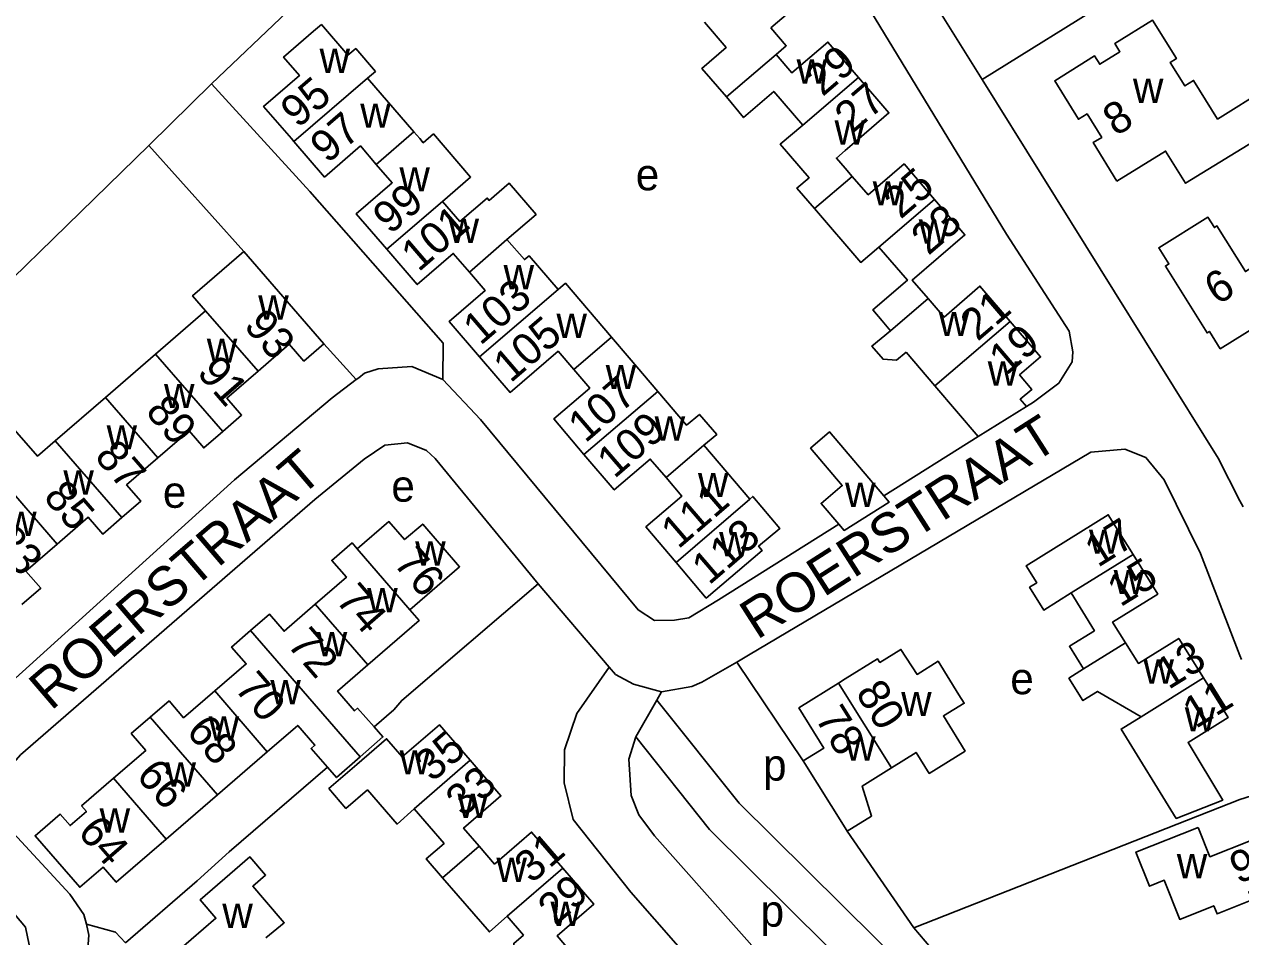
# Model space of a CAD drawing. Extents: x 156721 to 158827, y 386657 to 388950.
# Drawn here: x 157896 to 158050.1, y 388148.8 to 388264.5 of the extents above; entities that cross this region are included whole.
import ezdxf

# ---------------------------------------------------------------- set-up
doc = ezdxf.new("R2010")
doc.units = 0
for name, color, linetype in [('BLT_Basislijn', 7, 'Continuous'), ('BLT_Bebouwing', 7, 'Continuous'), ('BLT_Centroide', 7, 'Continuous'), ('BLT_Huisnummer', 7, 'Continuous'), ('BLT_Huisnummer_ tussenligend', 7, 'Continuous'), ('BLT_Huisnummer_zonder_bebouwing', 7, 'Continuous'), ('BLT_Onderverdeling_panden', 7, 'Continuous'), ('BLT_Plantopo', 7, 'Continuous'), ('BLT_Straatnaam', 7, 'Continuous')]:
    doc.layers.add(name, color=color, linetype=linetype)

msp = doc.modelspace()

# ---------------------------------------------------------------- linework, layer by layer
at = {"layer": 'BLT_Basislijn'}
for p, q in [((157993.68, 388295.39), (158017.34, 388257.5)), ((158017.34, 388257.5), (158045.78, 388275.22)), ((157929.27, 388266.07), (157919.68, 388256.96)), ((157923.79, 388235.71), (157911.73, 388249.12)), ((157933.93, 388224), (157938.04, 388219.45)), ((158004.88, 388204.72), (158016.83, 388212.25)), ((158047.24, 388209.52), (158050, 388204.11)), ((158050, 388204.11), (158050.4, 388203.33)), ((157970.07, 388182.99), (157961.07, 388193.57)), ((157994.68, 388171.14), (157986.24, 388183.65)), ((158050.2, 388183.97), (158050, 388184.5)), ((157973.44, 388174.16), (157976.11, 388178.83)), ((157976.11, 388178.83), (157976.72, 388179.89)), ((158050, 388166.22), (158008.68, 388149.97)), ((158054.58, 388167.7), (158050, 388166.22)), ((158008.68, 388149.97), (158000.25, 388162.24))]:
    msp.add_line(p, q, dxfattribs=at)
for points in [[(158022.96, 388216.06), (158023.83, 388216.61), (158027.07, 388219.02), (158028.73, 388221.73), (158028.85, 388222.96), (158028.35, 388225.6), (158020.44, 388237.9), (158003.19, 388266.21)], [(158047.24, 388209.52), (158017.34, 388257.5)], [(157919.68, 388256.96), (157911.85, 388249.23), (157911.73, 388249.12)], [(157919.68, 388256.96), (157932.15, 388243.31), (157949.03, 388224.09), (157949.01, 388219.47)], [(157911.73, 388249.12), (157882.37, 388220.49), (157874.02, 388212.6)], [(157949.01, 388219.47), (157945.06, 388221.11), (157940.82, 388220.82), (157939.06, 388220.29), (157938.36, 388219.69), (157938.04, 388219.45)], [(157938.04, 388219.45), (157934.97, 388217.16), (157922.62, 388206.75), (157885.4, 388173.07)], [(157949.01, 388219.47), (157953.79, 388214.4), (157973.74, 388190.26), (157975.82, 388188.93), (157978.35, 388188.95), (157980.19, 388189.25), (157983.94, 388191.54), (157999.18, 388201.13)], [(157961.07, 388193.57), (157948.03, 388209.47), (157946.92, 388210.49), (157944.52, 388211.45), (157941.65, 388211.16), (157939.05, 388209.37), (157932.79, 388204.28), (157922.65, 388195.48), (157895.5, 388171.88), (157892.26, 388168.26), (157892.42, 388164.68), (157893.57, 388163.07), (157901.73, 388154.22), (157903.49, 388151.67), (157903.87, 388150.45)], [(158050, 388184.5), (158045.02, 388197.43), (158040.39, 388206.74), (158038.08, 388209.6), (158035.44, 388210.65), (158031.13, 388210.24), (157987.73, 388184.52), (157986.24, 388183.65)], [(157961.07, 388193.57), (157943.79, 388178.8), (157942.8, 388177.62), (157940.28, 388175.44)], [(157986.24, 388183.65), (157981.84, 388181.09), (157980.56, 388180.57), (157976.72, 388179.89)], [(157970.07, 388182.99), (157965.98, 388177.12), (157964.42, 388172.54), (157964.39, 388168.36), (157965.53, 388163.69), (157972.83, 388154.47), (157999.51, 388124.03), (158002.23, 388120.12), (158002.39, 388118.68), (158001.27, 388115.71), (157997.69, 388112.93), (157965.66, 388093.93), (157962.8, 388092.59), (157960.96, 388092.1), (157957.83, 388092.87)], [(157970.07, 388182.99), (157970.87, 388182.09), (157973.18, 388180.84), (157976.72, 388179.89)], [(157976.11, 388178.83), (157986.54, 388165.79), (158025.6, 388127.11)], [(158010.2, 388122.9), (157975.83, 388161.63), (157973.85, 388164.28), (157972.85, 388166.74), (157972.56, 388171.34), (157973.44, 388174.16)], [(157973.44, 388174.16), (157982.81, 388162.44), (158022.68, 388122.9)], [(157934.37, 388170.33), (157921.93, 388159.59), (157917.86, 388155.92), (157908.79, 388148.08)], [(157888.63, 388139.49), (157895.79, 388145.91), (157896.6, 388147.82), (157896.14, 388150.07), (157884.39, 388163.96), (157883.64, 388166.77)], [(157903.87, 388150.45), (157904.16, 388149.04), (157903.82, 388144.5), (157902.45, 388141.9)], [(157903.87, 388150.45), (157907.51, 388149.42), (157908.79, 388148.08)], [(158008.68, 388149.97), (158015.88, 388141.51), (158016.04, 388141.01), (158025.6, 388127.11)]]:
    msp.add_lwpolyline(points, dxfattribs=at)
at = {"layer": 'BLT_Bebouwing'}
for p, q in [((157923.79, 388235.71), (157933.93, 388224)), ((157912.6, 388222.7), (157918.94, 388228.19)), ((157906.25, 388217.2), (157912.6, 388222.7)), ((157899.89, 388211.69), (157906.25, 388217.2)), ((157926.75, 388172.27), (157920.43, 388166.81)), ((157920.43, 388166.81), (157913.96, 388161.22))]:
    msp.add_line(p, q, dxfattribs=at)
for points in [[(157990.57, 388264.06), (157995.88, 388268.59), (157991.97, 388273.17)], [(157930.14, 388249.62), (157929.81, 388250), (157926.28, 388254.09), (157930.83, 388258), (157928.82, 388260.34), (157932.61, 388263.6), (157933.61, 388264.45), (157936.98, 388260.56), (157937.97, 388261.41), (157940.47, 388258.52), (157939.46, 388257.65)], [(157982.14, 388264.76), (157984.9, 388261.53), (157981.84, 388258.89), (157984.94, 388255.29)], [(157991.23, 388260.66), (157992.52, 388261.77), (157990.57, 388264.06)], [(158001.66, 388257.75), (157997.8, 388262.24), (157993.23, 388258.32), (157991.23, 388260.66)], [(157939.46, 388257.65), (157945.33, 388250.86)], [(158001.66, 388257.75), (158005.52, 388253.26), (158001.74, 388250), (158000, 388248.5), (157998.88, 388247.54), (158000, 388246.24), (158000.88, 388245.21)], [(157984.94, 388255.29), (157987.12, 388252.67), (157990.94, 388255.98), (157994.63, 388251.7)], [(157994.63, 388251.7), (157991.76, 388249.29), (157995.42, 388245.05), (157993.88, 388243.73), (157996.09, 388241.15)], [(157940.57, 388246.74), (157938.56, 388249.07), (157934.01, 388245.12), (157930.14, 388249.62)], [(157945.33, 388250.86), (157946.07, 388250), (157946.52, 388249.48), (157947.81, 388250.6), (157952.52, 388245.13), (157948.96, 388242.05)], [(157941.91, 388235.98), (157938.04, 388240.47), (157942.59, 388244.41), (157940.57, 388246.74)], [(158011.29, 388242.3), (158007.44, 388246.8), (158002.9, 388242.88), (158000.88, 388245.21)], [(157948.96, 388242.05), (157951.17, 388239.48), (157954.63, 388242.46), (157954.87, 388242.17), (157957.41, 388244.35), (157960.81, 388240.4), (157957.12, 388237.22)], [(158010.49, 388229.73), (158008.48, 388232.07), (158015.15, 388237.8), (158011.29, 388242.3)], [(157996.09, 388241.15), (158001.95, 388234.31), (158004.25, 388236.26)], [(157957.12, 388237.22), (157959.35, 388234.66), (157959.94, 388235.16), (157963.61, 388230.87)], [(157918.94, 388228.19), (157917.3, 388230.08), (157923.79, 388235.71)], [(157952.37, 388233.08), (157950.33, 388235.45), (157945.76, 388231.5), (157941.91, 388235.98)], [(158004.25, 388236.26), (158007.87, 388232.04), (158003.49, 388228.28), (158004.67, 388226.9), (158005.74, 388225.64)], [(157953.66, 388222.33), (157949.8, 388226.81), (157954.38, 388230.77), (157952.37, 388233.08)], [(157963.61, 388230.87), (157964.53, 388231.66), (157970.39, 388224.82)], [(158020.9, 388226.82), (158017.07, 388231.31), (158012.51, 388227.39), (158010.49, 388229.73)], [(158022.96, 388216.06), (158022.18, 388216.96), (158023.65, 388218.22), (158022.08, 388220.06), (158024.74, 388222.34), (158020.9, 388226.82)], [(157970.39, 388224.82), (157972.61, 388222.23), (157976.24, 388217.94)], [(158005.74, 388225.64), (158003.37, 388223.7), (158004.78, 388222.04), (158006.5, 388221.91), (158007.71, 388222.93)], [(157933.93, 388224), (157931.39, 388221.8), (157929.54, 388223.93), (157925.59, 388220.51)], [(157965.6, 388220.72), (157963.6, 388223.06), (157957.52, 388217.84), (157953.66, 388222.33)], [(158007.71, 388222.93), (158011.36, 388218.66)], [(157925.59, 388220.51), (157921.65, 388217.09), (157923.5, 388214.95), (157921.11, 388212.88)], [(157966.89, 388209.97), (157963.05, 388214.47), (157967.61, 388218.38), (157965.6, 388220.72)], [(158011.36, 388218.66), (158016.83, 388212.25)], [(157976.24, 388217.94), (157979.89, 388213.67), (157981.51, 388215.05), (157983.71, 388212.51), (157982.06, 388211.13)], [(158016.83, 388212.25), (158022.96, 388216.06)], [(157890.36, 388209.89), (157894.45, 388213.43), (157897.64, 388209.75), (157899.89, 388211.69)], [(157921.11, 388212.88), (157918.71, 388210.8), (157916.84, 388212.97), (157912.88, 388209.54)], [(157999.18, 388201.13), (157996.93, 388203.76), (157999.61, 388206.03), (157995.6, 388210.76), (157998.01, 388212.83), (158004.88, 388204.72)], [(157982.06, 388211.13), (157987.89, 388204.32)], [(157912.88, 388209.54), (157908.93, 388206.11), (157910.72, 388204.04), (157908.32, 388201.96)], [(157977.29, 388207.04), (157975.29, 388209.38), (157970.73, 388205.47), (157966.89, 388209.97)], [(157978.56, 388196.28), (157974.73, 388200.79), (157979.29, 388204.7), (157977.29, 388207.04)], [(157987.89, 388204.32), (157988.28, 388204.65), (157991.7, 388200.58), (157989.01, 388198.33), (157989.46, 388197.79), (157982.39, 388191.77), (157978.56, 388196.28)], [(158004.88, 388204.72), (158005.56, 388203.92), (157999.85, 388200.35), (157999.18, 388201.13)], [(157908.32, 388201.96), (157905.91, 388199.87), (157904.07, 388202), (157900.12, 388198.58)], [(158028.61, 388192.41), (158025.14, 388190.24), (158023.35, 388193.14), (158024.26, 388193.71), (158022.92, 388195.85), (158033.33, 388202.33), (158036.46, 388197.3)], [(157938.16, 388197.99), (157942.18, 388201.46), (157944.16, 388199.17), (157946.45, 388201.15), (157951.13, 388195.74), (157944.81, 388190.28)], [(157900.12, 388198.58), (157896.18, 388195.17), (157898.05, 388193.01), (157895.65, 388190.94)], [(157932.83, 388190.98), (157936.78, 388194.4), (157934.93, 388196.53), (157937.5, 388198.75), (157938.16, 388197.99)], [(158036.46, 388197.3), (158039.59, 388192.27), (158033.88, 388188.72), (158035.51, 388186.1)], [(158030.19, 388182.79), (158028.4, 388185.67), (158031.56, 388187.63), (158028.61, 388192.41)], [(157924.64, 388187.64), (157927.04, 388189.71), (157928.89, 388187.57), (157932.83, 388190.98)], [(157944.81, 388190.28), (157946, 388188.91), (157939.49, 388183.29)], [(157920.12, 388180), (157924.09, 388183.41), (157922.24, 388185.56), (157924.64, 388187.64)], [(158035.51, 388186.1), (158037.14, 388183.48), (158042.25, 388186.66), (158045.38, 388181.64)], [(157999.13, 388180.97), (158000, 388181.51), (158004.1, 388184.06), (158004.39, 388183.6), (158007.05, 388185.25), (158009.09, 388182.08), (158011.75, 388183.75), (158014.4, 388179.51), (158015.07, 388178.43), (158012.43, 388176.82), (158015.17, 388172.38), (158010.65, 388169.55), (158008.98, 388172.21), (158005.84, 388170.24)], [(157939.49, 388183.29), (157935.66, 388179.97), (157937.83, 388177.46), (157938.21, 388177.8), (157940.28, 388175.44)], [(158037.51, 388176.73), (158031.96, 388179.93), (158030.11, 388178.77), (158028.34, 388181.6), (158030.19, 388182.79)], [(158045.38, 388181.64), (158048.51, 388176.61), (158043.43, 388173.47), (158047.83, 388166.17), (158041.94, 388163.84), (158034.94, 388175.16), (158037.51, 388176.73)], [(157994.68, 388171.14), (157997.29, 388172.75), (157994.12, 388177.85), (157999.13, 388180.97)], [(157911.92, 388176.66), (157914.31, 388178.73), (157916.15, 388176.59), (157920.12, 388180)], [(157907.29, 388168.95), (157911.36, 388172.46), (157909.52, 388174.6), (157911.92, 388176.66)], [(157934.37, 388170.33), (157932.3, 388172.69), (157932.79, 388173.11), (157930.62, 388175.62), (157926.75, 388172.27)], [(157952.46, 388171.2), (157948.56, 388175.71), (157943.85, 388171.64), (157941.87, 388173.94), (157938.09, 388170.67), (157934.56, 388167.61), (157936.73, 388165.11), (157939.45, 388167.46), (157943.2, 388163.11), (157945.36, 388165.06)], [(157940.28, 388175.44), (157941.4, 388174.17), (157938.53, 388171.65)], [(157938.53, 388171.65), (157935.53, 388169.01), (157934.37, 388170.33)], [(157952.46, 388171.2), (157956.36, 388166.7), (157951.63, 388162.61), (157953.6, 388160.34)], [(158000.25, 388162.24), (158000, 388162.64), (157994.68, 388171.14)], [(158005.84, 388170.24), (158002.14, 388167.94), (158003.34, 388164.14), (158000.25, 388162.24)], [(157913.96, 388161.22), (157907.62, 388155.74), (157905.95, 388157.67), (157902.99, 388155.12), (157897.33, 388161.65), (157900.51, 388164.39), (157901.77, 388162.93), (157903.84, 388164.71), (157903.22, 388165.43), (157907.29, 388168.95)], [(157945.36, 388165.06), (157949.16, 388160.67), (157946.89, 388158.71), (157948.96, 388156.32)], [(157953.6, 388160.34), (157955.57, 388158.06), (157960.24, 388162.11), (157964.2, 388157.54)], [(157919.46, 388142.58), (157915.54, 388147.12), (157920.24, 388151.18), (157918.24, 388153.5), (157922.02, 388156.77), (157924.56, 388158.96), (157926.55, 388156.65), (157924.91, 388155.23), (157926.4, 388153.51), (157928.9, 388150.62), (157926.58, 388148.72)], [(157964.2, 388157.54), (157968.15, 388152.98), (157963.48, 388148.94), (157965.44, 388146.66)], [(157948.96, 388156.32), (157954.9, 388149.45), (157957.14, 388151.44)], [(157957.14, 388151.44), (157959.21, 388149.05), (157957.99, 388147.99), (157957.92, 388146.21), (157958.91, 388145.07), (157957.98, 388144.27), (157959.98, 388141.96), (157960.79, 388142.64)]]:
    msp.add_lwpolyline(points, dxfattribs=at)
for points in [[(158034.42, 388244.61), (158040.59, 388248.43), (158043.12, 388244.35), (158055.96, 388252.22), (158053.39, 388256.35), (158047.18, 388252.48), (158044.13, 388257.37), (158043.03, 388256.68), (158041.18, 388259.66), (158041.95, 388260.14), (158038.91, 388265.02), (158034.16, 388262.07), (158034.81, 388261.02), (158032.25, 388259.43), (158031.6, 388260.48), (158026.54, 388257.33), (158029.55, 388252.46), (158030.64, 388253.14), (158032.49, 388250.16), (158031.41, 388249.49)], [(158044.71, 388162.69), (158046.2, 388158.97), (158051.31, 388161.01), (158053.51, 388155.44), (158051.13, 388154.52), (158051.55, 388153.5), (158047.11, 388151.74), (158046.7, 388152.76), (158042.39, 388151.04), (158040.41, 388155.99), (158038.55, 388155.25), (158036.82, 388159.57)]]:
    msp.add_lwpolyline(points, close=True, dxfattribs=at)
at = {"layer": 'BLT_Onderverdeling_panden'}
for p, q in [((157984.94, 388255.29), (157991.23, 388260.66)), ((157939.46, 388257.65), (157930.14, 388249.62)), ((158001.66, 388257.75), (157994.63, 388251.7)), ((157940.57, 388246.74), (157945.33, 388250.86)), ((158000.88, 388245.21), (157996.09, 388241.15)), ((157948.96, 388242.05), (157941.91, 388235.98)), ((158011.29, 388242.3), (158004.25, 388236.26)), ((157957.12, 388237.22), (157952.37, 388233.08)), ((157953.66, 388222.33), (157963.61, 388230.87)), ((158010.49, 388229.73), (158005.74, 388225.64)), ((157925.59, 388220.51), (157918.94, 388228.19)), ((158020.9, 388226.82), (158011.36, 388218.66)), ((157970.39, 388224.82), (157965.6, 388220.72)), ((157921.11, 388212.88), (157912.6, 388222.7)), ((157912.88, 388209.54), (157906.25, 388217.2)), ((157966.89, 388209.97), (157976.24, 388217.94)), ((157908.32, 388201.96), (157899.89, 388211.69)), ((157977.29, 388207.04), (157982.06, 388211.13)), ((157900.12, 388198.58), (157890.36, 388209.89)), ((157978.56, 388196.28), (157987.89, 388204.32)), ((157938.16, 388197.99), (157944.81, 388190.28)), ((158036.46, 388197.3), (158028.61, 388192.41)), ((157932.83, 388190.98), (157939.49, 388183.29)), ((157924.64, 388187.64), (157938.53, 388171.65)), ((158035.51, 388186.1), (158030.19, 388182.79)), ((158045.38, 388181.64), (158037.51, 388176.73)), ((158005.84, 388170.24), (157999.13, 388180.97)), ((157920.12, 388180), (157926.75, 388172.27)), ((157911.92, 388176.66), (157920.43, 388166.81)), ((157952.46, 388171.2), (157945.36, 388165.06)), ((157907.29, 388168.95), (157913.96, 388161.22)), ((157953.6, 388160.34), (157948.96, 388156.32)), ((157964.2, 388157.54), (157957.14, 388151.44))]:
    msp.add_line(p, q, dxfattribs=at)
at = {"layer": 'BLT_Plantopo'}
msp.add_lwpolyline([(158061.46, 388250), (158057.48, 388247.52), (158062.78, 388238.99), (158057.54, 388235.73), (158056.8, 388236.93), (158050.7, 388233.14), (158047.1, 388238.93), (158046.77, 388238.72), (158045.95, 388240.04), (158039.73, 388236.17), (158041, 388234.12), (158040.57, 388233.85), (158045.84, 388225.37), (158046.15, 388225.56), (158047.52, 388223.36), (158057.77, 388229.74), (158058.09, 388229.23), (158068.58, 388235.75), (158068.13, 388236.46), (158069.4, 388237.25)], dxfattribs=at)

# ---------------------------------------------------------------- texts
at = {"layer": 'BLT_Centroide'}
for s, p in [('w', (157933.38, 388258.33)), ('w', (157993.83, 388256.97)), ('w', (158036.45, 388254.53)), ('w', (157938.53, 388251.38)), ('w', (157998.64, 388249.23)), ('w', (157943.5, 388243.31)), ('e', (157973.45, 388243.45)), ('w', (158003.47, 388241.53)), ('w', (157949.72, 388236.78)), ('w', (158009.31, 388236.69)), ('w', (157956.7, 388230.89)), ('w', (157925.61, 388227.06)), ('w', (158011.84, 388224.97)), ('w', (157963.4, 388224.75)), ('w', (157919.09, 388221.59)), ('w', (158018.05, 388218.69)), ('w', (157969.64, 388218.25)), ('w', (157913.67, 388215.84)), ('w', (157975.84, 388211.72)), ('w', (157906.39, 388210.61)), ('w', (157900.92, 388204.89)), ('e', (157913.53, 388203.21)), ('e', (157942.48, 388203.98)), ('w', (157981.33, 388204.56)), ('w', (157999.97, 388203.31)), ('w', (157893.66, 388199.64)), ('w', (157984.02, 388197.06)), ('w', (158030.88, 388197.38)), ('w', (157945.5, 388195.88)), ('w', (158034, 388192.27)), ('w', (157939.42, 388189.95)), ('w', (157933.02, 388184.39)), ('w', (158037.78, 388180.91)), ('e', (158020.91, 388179.58)), ('w', (157927.14, 388178.31)), ('w', (158007.08, 388176.81)), ('w', (158043.02, 388174.86)), ('w', (157919.33, 388173.7)), ('w', (157999.97, 388171.16)), ('w', (157943.52, 388169.41)), ('w', (157913.86, 388167.88)), ('p', (157989.58, 388168.63)), ('w', (157950.86, 388163.89)), ('w', (157905.51, 388162.03)), ('w', (157955.79, 388155.78)), ('w', (158042.01, 388156.26)), ('w', (157921.06, 388149.94)), ('w', (157962.64, 388150.22)), ('p', (157989.27, 388150.12))]:
    msp.add_text(s, height=4, dxfattribs=at).set_placement(p)
at = {"layer": 'BLT_Huisnummer'}
for s, rotation, p in [('95', 40.7168, (157930.63, 388251.22)), ('27', 40.5342, (158000.83, 388250.52)), ('8', 31.8291, (158034.28, 388250.23)), ('99', 40.7168, (157942.33, 388237.75)), ('23', 40.5342, (158010.52, 388235.11)), ('103', 40.7168, (157953.76, 388223.7)), ('93', 310.885, (157923.66, 388226.21)), ('19', 40.5342, (158020.39, 388219.88)), ('107', 40.7168, (157967.06, 388211.33)), ('87', 310.885, (157904.74, 388209.62)), ('17', 31.8951, (158032, 388195.57)), ('83', 310.885, (157891.7, 388198.82)), ('113', 40.7168, (157982.74, 388193.32)), ('76', 310.9204, (157942.61, 388196.12)), ('72', 310.9204, (157929.14, 388185.83)), ('80', 302.0981, (158001.22, 388179.76)), ('11', 31.7626, (158044.4, 388175.14)), ('78', 301.9011, (157996.09, 388176.54)), ('68', 310.9204, (157916.35, 388174.8)), ('35', 40.8539, (157947.67, 388168.34)), ('64', 310.9204, (157902.6, 388162.02)), ('9', 21.7626, (158049.75, 388155.5)), ('29', 40.863, (157963.24, 388150.14))]:
    msp.add_text(s, height=4, rotation=rotation, dxfattribs=at).set_placement(p)
at = {"layer": 'BLT_Huisnummer_ tussenligend'}
for s, rotation, p in [('29', 40.5342, (157997.12, 388255.24)), ('97', 40.7168, (157934.38, 388246.74)), ('25', 40.5342, (158007.01, 388239.7)), ('101', 40.7168, (157945.92, 388233.01)), ('21', 40.5342, (158016.76, 388224.22)), ('105', 40.7168, (157957.58, 388218.94)), ('91', 310.9014, (157917.72, 388220.28)), ('89', 310.9014, (157911.19, 388215.33)), ('109', 40.7168, (157970.74, 388206.82)), ('85', 310.9014, (157898.26, 388204.5)), ('111', 40.7168, (157978.84, 388197.89)), ('15', 31.7626, (158034.85, 388190.56)), ('74', 310.9204, (157935.29, 388191.44)), ('13', 31.7626, (158040.96, 388180.09)), ('70', 310.9204, (157922.47, 388180.26)), ('66', 310.9204, (157910.01, 388169.2)), ('33', 40.8533, (157951.57, 388163.9)), ('31', 40.8533, (157960.26, 388155.48))]:
    msp.add_text(s, height=4, rotation=rotation, dxfattribs=at).set_placement(p)
at = {"layer": 'BLT_Huisnummer_zonder_bebouwing'}
msp.add_text('6', height=4, rotation=31.8291, dxfattribs=at).set_placement((158047.14, 388228.82))
at = {"layer": 'BLT_Straatnaam'}
for rotation, p in [(32.5822, (157988.81, 388186.41)), (40.6104, (157899.35, 388177.4))]:
    msp.add_text('ROERSTRAAT', height=5, rotation=rotation, dxfattribs=at).set_placement(p)

doc.saveas('drawing.dxf')
